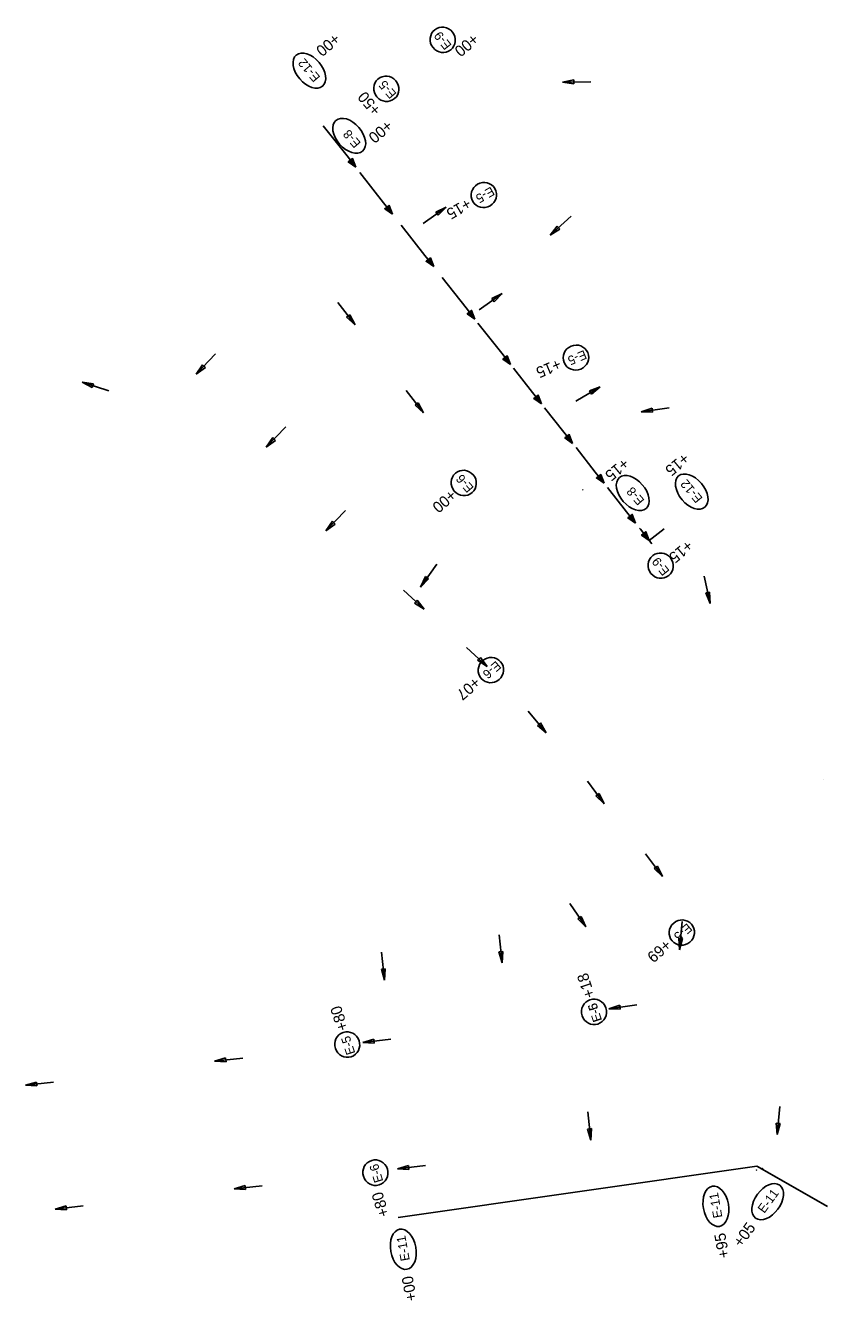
# Model space of a CAD drawing. Extents: x 918344 to 920005, y 1764082 to 1766125.
# Drawn here: x 918971 to 919402, y 1764408 to 1765094 of the extents above; entities that cross this region are included whole.
import ezdxf

# ---------------------------------------------------------------- set-up
doc = ezdxf.new("R2010")
doc.units = 0
for name, color, linetype in [('1', 7, 'Continuous'), ('43', 7, 'Continuous'), ('44', 7, 'Continuous'), ('EC_CG', 7, 'Continuous'), ('Level 1', 7, 'Continuous'), ('Level 44', 7, 'Continuous'), ('Level 8', 7, 'Continuous'), ('R_Special Ditch', 7, 'Continuous'), ('S_MSC_PT_SYM', 7, 'Continuous')]:
    doc.layers.add(name, color=color, linetype=linetype)

msp = doc.modelspace()

# ---------------------------------------------------------------- linework, layer by layer
at = {"layer": '1'}
for centre, major_axis, ratio in [((919195, 1765086.1), (4.3, -5.37), 0.97521), ((919123.29, 1765069.54), (-7.06, 8.38), 0.622952), ((919144.71, 1765034.5), (-7.2, 8.26), 0.622952), ((919297.17, 1764842.35), (-7.2, 8.26), 0.622952), ((919328.89, 1764843.14), (-7.06, 8.38), 0.622952), ((919312.18, 1764803.29), (4.3, -5.37), 0.97521)]:
    msp.add_ellipse(centre, major_axis=major_axis, ratio=ratio, dxfattribs=at)
at = {"layer": '43'}
for p, q in [((919259.46, 1765063.39), (919265.53, 1765064.5)), ((919265.54, 1765062.35), (919259.46, 1765063.39)), ((919265.53, 1765064.5), (919265.54, 1765062.35)), ((919191.2, 1764993.45), (919196.76, 1764996.11)), ((919192.45, 1764991.71), (919191.2, 1764993.45)), ((919196.76, 1764996.11), (919192.45, 1764991.71)), ((919252.79, 1764981), (919256.56, 1764985.88)), ((919258.01, 1764984.29), (919252.79, 1764981)), ((919256.56, 1764985.88), (919258.01, 1764984.29)), ((919221.39, 1764946.98), (919226.96, 1764949.64)), ((919222.64, 1764945.24), (919221.39, 1764946.98)), ((919226.96, 1764949.64), (919222.64, 1764945.24)), ((919143.3, 1764936.92), (919145, 1764938.23)), ((919145, 1764938.23), (919147.88, 1764932.78)), ((919147.88, 1764932.78), (919143.3, 1764936.92)), ((919062.37, 1764906.19), (919065.8, 1764911.31)), ((919065.8, 1764911.31), (919067.35, 1764909.83)), ((919067.35, 1764909.83), (919062.37, 1764906.19)), ((919001.03, 1764901.98), (919007.14, 1764901.13)), ((919006.48, 1764899.09), (919001.03, 1764901.98)), ((919007.14, 1764901.13), (919006.48, 1764899.09)), ((919273.92, 1764897.34), (919279.72, 1764899.46)), ((919275, 1764895.48), (919273.92, 1764897.34)), ((919279.72, 1764899.46), (919275, 1764895.48)), ((919180.09, 1764889.54), (919181.78, 1764890.86)), ((919181.78, 1764890.86), (919184.66, 1764885.4)), ((919184.66, 1764885.4), (919180.09, 1764889.54)), ((919301.65, 1764885.99), (919307.52, 1764887.9)), ((919307.82, 1764885.77), (919301.65, 1764885.99)), ((919307.52, 1764887.9), (919307.82, 1764885.77)), ((919100.12, 1764867.03), (919103.55, 1764872.16)), ((919105.1, 1764870.68), (919100.12, 1764867.03)), ((919103.55, 1764872.16), (919105.1, 1764870.68)), ((919132.2, 1764822.02), (919135.63, 1764827.15)), ((919137.18, 1764825.66), (919132.2, 1764822.02)), ((919135.63, 1764827.15), (919137.18, 1764825.66)), ((919183, 1764791.78), (919185.64, 1764797.36)), ((919187.39, 1764796.11), (919183, 1764791.78)), ((919185.64, 1764797.36), (919187.39, 1764796.11)), ((919336.43, 1764788.59), (919338.52, 1764789.05)), ((919338.8, 1764782.89), (919336.43, 1764788.59)), ((919338.52, 1764789.05), (919338.8, 1764782.89)), ((919179.83, 1764783.16), (919181.29, 1764784.73)), ((919185.02, 1764779.83), (919179.83, 1764783.16)), ((919181.29, 1764784.73), (919185.02, 1764779.83)), ((919213.76, 1764752.38), (919215.22, 1764753.96)), ((919215.22, 1764753.96), (919218.96, 1764749.05)), ((919218.96, 1764749.05), (919213.76, 1764752.38)), ((919245.99, 1764717.38), (919247.64, 1764718.75)), ((919247.64, 1764718.75), (919250.69, 1764713.39)), ((919250.69, 1764713.39), (919245.99, 1764717.38)), ((919277.32, 1764679.48), (919279.04, 1764680.76)), ((919281.8, 1764675.24), (919277.32, 1764679.48)), ((919279.04, 1764680.76), (919281.8, 1764675.24)), ((919308.67, 1764640.38), (919310.39, 1764641.66)), ((919313.14, 1764636.14), (919308.67, 1764640.38)), ((919310.39, 1764641.66), (919313.14, 1764636.14)), ((919267.57, 1764613.41), (919269.35, 1764614.61)), ((919271.87, 1764608.98), (919267.57, 1764613.41)), ((919269.35, 1764614.61), (919271.87, 1764608.98)), ((919322.38, 1764596.75), (919321.86, 1764602.9)), ((919321.86, 1764602.9), (919324, 1764602.7)), ((919324, 1764602.7), (919322.38, 1764596.75)), ((919225.22, 1764595.61), (919227.36, 1764595.83)), ((919226.92, 1764589.68), (919225.22, 1764595.61)), ((919227.36, 1764595.83), (919226.92, 1764589.68)), ((919161.98, 1764586.27), (919164.12, 1764586.49)), ((919163.68, 1764580.34), (919161.98, 1764586.27)), ((919164.12, 1764586.49), (919163.68, 1764580.34)), ((919284.27, 1764564.94), (919290.14, 1764566.84)), ((919290.43, 1764564.71), (919284.27, 1764564.94)), ((919290.14, 1764566.84), (919290.43, 1764564.71)), ((919151.97, 1764546.86), (919157.88, 1764548.62)), ((919157.88, 1764548.62), (919158.13, 1764546.48)), ((919158.13, 1764546.48), (919151.97, 1764546.86)), ((919072.35, 1764536.74), (919078.26, 1764538.5)), ((919078.51, 1764536.37), (919072.35, 1764536.74)), ((919078.26, 1764538.5), (919078.51, 1764536.37)), ((918970.64, 1764523.81), (918976.56, 1764525.56)), ((918976.8, 1764523.43), (918970.64, 1764523.81)), ((918976.56, 1764525.56), (918976.8, 1764523.43)), ((919272.89, 1764500.29), (919275.03, 1764500.52)), ((919274.62, 1764494.37), (919272.89, 1764500.29)), ((919275.03, 1764500.52), (919274.62, 1764494.37)), ((919374.86, 1764497.27), (919374.36, 1764503.42)), ((919374.36, 1764503.42), (919376.5, 1764503.22)), ((919376.5, 1764503.22), (919374.86, 1764497.27)), ((919170.62, 1764478.92), (919176.53, 1764480.67)), ((919176.78, 1764478.54), (919170.62, 1764478.92)), ((919176.53, 1764480.67), (919176.78, 1764478.54)), ((919082.79, 1764468.1), (919088.7, 1764469.85)), ((919088.95, 1764467.72), (919082.79, 1764468.1)), ((919088.7, 1764469.85), (919088.95, 1764467.72)), ((918986.54, 1764457.19), (918992.45, 1764458.94)), ((918992.45, 1764458.94), (918992.69, 1764456.81)), ((918992.69, 1764456.81), (918986.54, 1764457.19))]:
    msp.add_line(p, q, dxfattribs=at)
for points in [[(919274.65, 1765063.47), (919259.46, 1765063.39)], [(919184.41, 1764987.28), (919196.76, 1764996.11)], [(919264.02, 1764991.22), (919252.79, 1764981)], [(919214.6, 1764940.81), (919226.96, 1764949.64)], [(919138.56, 1764944.77), (919147.88, 1764932.78)], [(919072.89, 1764917.15), (919062.37, 1764906.19)], [(919015.48, 1764897.29), (919001.03, 1764901.98)], [(919175.35, 1764897.4), (919184.66, 1764885.4)], [(919266.58, 1764891.83), (919279.72, 1764899.46)], [(919316.69, 1764888.11), (919301.65, 1764885.99)], [(919110.63, 1764877.99), (919100.12, 1764867.03)], [(919142.72, 1764832.98), (919132.2, 1764822.02)], [(919191.79, 1764804.16), (919183, 1764791.78)], [(919335.49, 1764797.71), (919338.8, 1764782.89)], [(919173.86, 1764790.13), (919185.02, 1764779.83)], [(919207.8, 1764759.35), (919218.96, 1764749.05)], [(919240.98, 1764725.07), (919250.69, 1764713.39)], [(919272.76, 1764687.44), (919281.8, 1764675.24)], [(919304.1, 1764648.34), (919313.14, 1764636.14)], [(919263.36, 1764621.56), (919271.87, 1764608.98)], [(919323.76, 1764611.88), (919322.38, 1764596.75)], [(919225.34, 1764604.78), (919226.92, 1764589.68)], [(919162.1, 1764595.44), (919163.68, 1764580.34)], [(919299.31, 1764567.03), (919284.27, 1764564.94)], [(919167.06, 1764548.59), (919151.97, 1764546.86)], [(919087.44, 1764538.47), (919072.35, 1764536.74)], [(918985.73, 1764525.53), (918970.64, 1764523.81)], [(919272.97, 1764509.47), (919274.62, 1764494.37)], [(919376.28, 1764512.39), (919374.86, 1764497.27)], [(919185.71, 1764480.64), (919170.62, 1764478.92)], [(919097.88, 1764469.82), (919082.79, 1764468.1)], [(919001.63, 1764458.91), (918986.54, 1764457.19)]]:
    msp.add_lwpolyline(points, dxfattribs=at)
at = {"layer": 'EC_CG'}
for p, q in [((919171.11, 1764452.63), (919363.96, 1764480.34)), ((919171.11, 1764452.63), (919363.96, 1764480.34)), ((919401.88, 1764458.67), (919363.96, 1764480.34)), ((919401.88, 1764458.67), (919363.96, 1764480.34)), ((919401.88, 1764458.67), (919363.96, 1764480.34)), ((919401.88, 1764458.67), (919364.65, 1764479.95))]:
    msp.add_line(p, q, dxfattribs=at)
for centre, major_axis, ratio in [((919220.9, 1764747.11), (5.22, 4.48), 0.97521), ((919323.54, 1764605.94), (5.22, 4.48), 0.97521), ((919276.31, 1764563.3), (2.14, -6.54), 0.97521), ((919276.31, 1764563.3), (2.14, -6.54), 0.97521), ((919143.62, 1764545.7), (2.14, -6.54), 0.97521), ((919158.79, 1764476.81), (2.01, -6.58), 0.97521), ((919369.71, 1764461.21), (6.46, 8.85), 0.622952), ((919341.9, 1764458.74), (-1.93, 10.79), 0.622952), ((919173.79, 1764435.61), (-1.96, 10.78), 0.622952), ((919173.79, 1764435.61), (-1.96, 10.78), 0.622952)]:
    msp.add_ellipse(centre, major_axis=major_axis, ratio=ratio, dxfattribs=at)
at = {"layer": 'Level 1'}
msp.add_line((919270.57, 1764844.24), (919270.08, 1764843.88), dxfattribs=at)
for centre, major_axis in [((919164.65, 1765059.74), (4.48, -5.22)), ((919217.11, 1765002.6), (5.95, 3.45)), ((919266.61, 1764915.17), (6.34, 2.68)), ((919206.28, 1764847.77), (4.48, -5.22))]:
    msp.add_ellipse(centre, major_axis=major_axis, ratio=0.97521, dxfattribs=at)
at = {"layer": 'Level 44'}
msp.add_line((919401.88, 1764458.67), (919364.65, 1764479.95), dxfattribs=at)
at = {"layer": 'Level 8'}
for p, q in [((919144.49, 1765020.63), (919147.32, 1765018.33)), ((919144.78, 1765020.86), (919147.38, 1765018.41)), ((919145.07, 1765021.09), (919147.45, 1765018.47)), ((919145.66, 1765021.54), (919147.61, 1765018.59)), ((919145.94, 1765021.76), (919147.69, 1765018.64)), ((919146.24, 1765021.99), (919147.78, 1765018.69)), ((919164.14, 1764995.45), (919166.96, 1764993.15)), ((919164.43, 1764995.68), (919167.03, 1764993.23)), ((919164.72, 1764995.91), (919167.1, 1764993.3)), ((919165.3, 1764996.36), (919167.25, 1764993.41)), ((919165.59, 1764996.58), (919167.34, 1764993.47)), ((919165.88, 1764996.81), (919167.42, 1764993.51)), ((919186.32, 1764967.2), (919189.15, 1764964.9)), ((919186.61, 1764967.43), (919189.21, 1764964.98)), ((919186.9, 1764967.66), (919189.28, 1764965.04)), ((919187.48, 1764968.11), (919189.44, 1764965.16)), ((919187.77, 1764968.33), (919189.52, 1764965.21)), ((919188.07, 1764968.56), (919189.6, 1764965.26)), ((919208.5, 1764938.95), (919211.33, 1764936.65)), ((919208.79, 1764939.18), (919211.39, 1764936.72)), ((919209.08, 1764939.4), (919211.46, 1764936.79)), ((919209.67, 1764939.86), (919211.62, 1764936.91)), ((919209.95, 1764940.08), (919211.7, 1764936.96)), ((919210.25, 1764940.31), (919211.79, 1764937)), ((919227.67, 1764914.51), (919230.5, 1764912.21)), ((919227.97, 1764914.74), (919230.56, 1764912.29)), ((919228.26, 1764914.97), (919230.63, 1764912.35)), ((919228.84, 1764915.42), (919230.79, 1764912.47)), ((919229.13, 1764915.64), (919230.87, 1764912.52)), ((919229.42, 1764915.87), (919230.96, 1764912.57)), ((919244.21, 1764893.44), (919247.04, 1764891.14)), ((919244.51, 1764893.67), (919247.11, 1764891.22)), ((919244.8, 1764893.9), (919247.18, 1764891.28)), ((919245.38, 1764894.35), (919247.33, 1764891.4)), ((919245.67, 1764894.57), (919247.42, 1764891.45)), ((919245.96, 1764894.8), (919247.5, 1764891.5)), ((919260.98, 1764872.17), (919263.81, 1764869.87)), ((919261.27, 1764872.4), (919263.87, 1764869.94)), ((919261.56, 1764872.62), (919263.94, 1764870.01)), ((919262.15, 1764873.08), (919264.1, 1764870.13)), ((919262.43, 1764873.3), (919264.18, 1764870.18)), ((919262.73, 1764873.53), (919264.27, 1764870.22)), ((919277.92, 1764850.67), (919280.75, 1764848.37)), ((919278.21, 1764850.9), (919280.81, 1764848.45)), ((919278.5, 1764851.13), (919280.88, 1764848.51)), ((919279.09, 1764851.58), (919281.04, 1764848.63)), ((919279.37, 1764851.8), (919281.12, 1764848.68)), ((919279.67, 1764852.03), (919281.21, 1764848.73)), ((919294.83, 1764829.22), (919297.66, 1764826.92)), ((919295.12, 1764829.45), (919297.72, 1764826.99)), ((919295.41, 1764829.67), (919297.79, 1764827.06)), ((919295.99, 1764830.13), (919297.95, 1764827.18)), ((919296.28, 1764830.35), (919298.03, 1764827.23)), ((919296.58, 1764830.58), (919298.11, 1764827.27)), ((919306.06, 1764816.82), (919313.98, 1764823.07)), ((919302.21, 1764819.9), (919305.03, 1764817.6)), ((919302.5, 1764820.13), (919305.1, 1764817.68)), ((919302.79, 1764820.36), (919305.17, 1764817.75)), ((919303.37, 1764820.81), (919305.32, 1764817.86)), ((919303.66, 1764821.04), (919305.41, 1764817.92)), ((919303.95, 1764821.27), (919305.49, 1764817.96)), ((919304.9, 1764818.24), (919307.41, 1764815.04))]:
    msp.add_line(p, q, dxfattribs=at)
for points in [[(919130.74, 1765039.9), (919143.53, 1765023.61), (919148.29, 1765017.55)], [(919150.39, 1765014.72), (919163.18, 1764998.43), (919167.94, 1764992.37)], [(919172.57, 1764986.47), (919185.36, 1764970.18), (919190.12, 1764964.12)], [(919194.75, 1764958.22), (919207.54, 1764941.93), (919212.3, 1764935.86)], [(919213.93, 1764933.78), (919226.72, 1764917.49), (919231.48, 1764911.43)], [(919232.98, 1764909.51), (919243.26, 1764896.42), (919248.02, 1764890.36)], [(919249.75, 1764888.24), (919260.02, 1764875.15), (919264.78, 1764869.09)], [(919266.69, 1764866.74), (919276.96, 1764853.65), (919281.72, 1764847.59)], [(919283.59, 1764845.29), (919293.87, 1764832.2), (919298.63, 1764826.13)], [(919289.71, 1764837.57), (919289.71, 1764837.57)], [(919300.87, 1764823.38), (919301.25, 1764822.89), (919306.01, 1764816.82)]]:
    msp.add_lwpolyline(points, dxfattribs=at)
for points in [[(919148.31, 1765017.53), (919144.19, 1765020.4), (919146.53, 1765022.22)], [(919167.96, 1764992.35), (919163.84, 1764995.23), (919166.18, 1764997.04)], [(919190.14, 1764964.09), (919186.02, 1764966.97), (919188.36, 1764968.79)], [(919212.32, 1764935.84), (919208.2, 1764938.72), (919210.54, 1764940.54)], [(919231.5, 1764911.4), (919227.38, 1764914.28), (919229.71, 1764916.1)], [(919248.04, 1764890.33), (919243.92, 1764893.21), (919246.26, 1764895.03)], [(919264.8, 1764869.06), (919260.68, 1764871.94), (919263.02, 1764873.76)], [(919281.74, 1764847.57), (919277.62, 1764850.44), (919279.96, 1764852.26)], [(919298.65, 1764826.11), (919294.53, 1764828.99), (919296.87, 1764830.81)], [(919306.03, 1764816.8), (919301.91, 1764819.68), (919304.25, 1764821.49)]]:
    msp.add_lwpolyline(points, close=True, dxfattribs=at)
at = {"layer": 'R_Special Ditch'}
msp.add_lwpolyline([(919399.5, 1764688.42), (919399.53, 1764688.44)], dxfattribs=at)
at = {"layer": 'S_MSC_PT_SYM'}
for points in [[(919366.93, 1764479.1), (919366.93, 1764479.15), (919366.93, 1764479.1), (919366.88, 1764479.1), (919366.93, 1764479.1), (919366.93, 1764479.05), (919366.93, 1764479.1), (919366.98, 1764479.1)], [(919363.66, 1764478.21), (919363.66, 1764478.26), (919363.66, 1764478.21), (919363.61, 1764478.21), (919363.66, 1764478.21), (919363.66, 1764478.16), (919363.66, 1764478.21), (919363.71, 1764478.21)]]:
    msp.add_lwpolyline(points, dxfattribs=at)

# ---------------------------------------------------------------- texts
at = {"layer": '1'}
for s, rotation, p in [('E-9 ', 128.65966, (919200.04, 1765083.2)), ('E-12', 130.14381, (919129.43, 1765066)), ('E-8 ', 131.04792, (919151.28, 1765030.61)), ('E-12', 130.14381, (919335.03, 1764839.6)), ('E-8 ', 131.04792, (919303.74, 1764838.46)), ('E-9 ', 128.65966, (919317.23, 1764800.39))]:
    msp.add_text(s, height=4.876, rotation=rotation, dxfattribs=at).set_placement(p)
at = {"layer": '44'}
for s, rotation, p in [('+00', 219.72636, (919136.74, 1765090)), ('+00', 219.76775, (919211.23, 1765089.84)), ('+50', 130.58924, (919162.18, 1765048.53)), ('+00', 219.72636, (919164.95, 1765043.3)), ('+15', 210.03565, (919208.14, 1765001.21)), ('+15', 202.85529, (919257.11, 1764914.78)), ('+15', 219.72636, (919292.17, 1764861.6)), ('+15', 219.72636, (919324.52, 1764864.31)), ('+00', 220.58924, (919199.17, 1764844.59)), ('+15', 219.76775, (919326.48, 1764817.46))]:
    msp.add_text(s, height=6, rotation=rotation, dxfattribs=at).set_placement(p)
at = {"layer": 'EC_CG'}
for s, height, rotation, p in [('E-6', 4.876, 220.64727, (919223.74, 1764752.35)), ('+07', 6, 220.58924, (919212.07, 1764743.88)), ('E-5', 4.876, 220.64727, (919326.48, 1764611.27)), ('+69', 6, 220.58924, (919314.71, 1764602.71)), ('+18', 6, 108.09976, (919276.97, 1764571.79)), ('+18', 6, 108.09976, (919276.97, 1764571.79)), ('E-6', 4.876, 108.15779, (919280.66, 1764558.87)), ('E-5', 4.876, 108.15779, (919280.7, 1764558.74)), ('+80', 6, 108.09976, (919144.28, 1764554.18)), ('E-5', 4.876, 108.15779, (919148.01, 1764541.14)), ('E-6', 4.876, 107.00883, (919163.05, 1764472.3)), ('+80', 6, 106.95081, (919166.32, 1764454)), ('E-11 ', 4.876, 100.16585, (919345.39, 1764452.87)), ('E-11 ', 4.876, 53.86662, (919367.88, 1764454.63)), ('+05', 6, 53.86978, (919355.5, 1764436.24)), ('E-11 ', 4.876, 100.31629, (919177.29, 1764429.75)), ('E-11 ', 4.876, 100.31629, (919177.29, 1764429.75)), ('+95', 6, 100.16901, (919349.21, 1764431.37)), ('+00', 6, 100.31945, (919181.16, 1764408.25)), ('+00', 6, 100.31945, (919181.16, 1764408.25))]:
    msp.add_text(s, height=height, rotation=rotation, dxfattribs=at).set_placement(p)
at = {"layer": 'Level 1'}
for s, rotation, p in [('E-5', 130.64727, (919170.44, 1765057.07)), ('E-5', 210.09367, (919220.98, 1765007.3)), ('E-5', 202.91331, (919271.04, 1764919.35)), ('E-6', 130.64727, (919211.99, 1764845.2))]:
    msp.add_text(s, height=4.876, rotation=rotation, dxfattribs=at).set_placement(p)

doc.saveas('drawing.dxf')
